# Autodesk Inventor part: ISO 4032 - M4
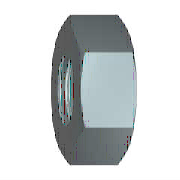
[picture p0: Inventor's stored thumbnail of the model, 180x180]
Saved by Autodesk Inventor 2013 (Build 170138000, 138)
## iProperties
Created: 2012-02
Part Number: ISO 4032 - M4
Material: Edelstahl, 440C
Description: Sechskantmuttern, Typ 1 - Produktklasse A und B
Document SubType Name: Modeling
Standard: ISO 4032
Designer: rYan
Standard Revision: Third edition 1999-08-15
Standards Organization: ISO
Language: de-DE
Size Designation: M4
Categories: <MemberInstance><Categories><Category DisplayName="Verbindungselemente" InternalName="e4da775c-781d-43d5-af7c-5136215cf5a6" Mnemonic="FSTN"><Category DisplayNam
Density: 7.75 g/cm^3
IsCustomPart: 0
Author: rYan
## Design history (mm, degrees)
sketch "Skizze1"
  geometry: L1 (-4.041, 0)-(-2.021, 3.5); L2 (-2.021, 3.5)-(2.021, 3.5); L3 (2.021, 3.5)-(4.041, 0); L4 (4.041, 0)-(2.021, -3.5); L5 (2.021, -3.5)-(-2.021, -3.5); L6 (-2.021, -3.5)-(-4.041, 0); 2 further points
  constraints: 12 end point, 1 coincident, 1 horizontal, 11 other
  dimensions: "d0" = 8.0829 distance of L3.end L1.start (= 1.1547 x SW)
extrude "Körper" new body sketch "Skizze1" distance "d1" = 3.2 (= KOH); taper "d2" = 0 deg
sketch "Skizze2"
  geometry: L1 (0, 2.021)-(0, 4.041) reference; L2 (0, 4.041)-(3.2, 4.041) reference; L3 (3.2, 2.021)-(3.2, 4.041) reference; L4 (-0.64, 0)-(3.84, 0) reference; L5 (0.63, 4.041)-(0, 2.95); L6 (2.57, 4.041)-(3.2, 2.95)
  constraints: 4 end point, 4 point on line
  dimensions: "d3" = 30 deg angle of L1 L5 (= ANG1); "d4" = 30 deg angle of L3 L6 (= ANG2); "d5" = 5.9 diameter of L5.end L4 (= SW0); "d6" = 5.9 diameter of L6.end L4 (= SW01)
revolve "Fase1" sketch "Skizze2" stored, may be unused: angle "d7" = 90 deg
sketch "Skizze3"
  geometry: 4 further points
  constraints: 1 coincident, 1 other
hole "Gewinde" sketch "Skizze3" at (0, 0) diameter "d25" = 3.242; stored, may be unused: countersink angle "d29" = 82 deg, drill point angle "d31" = 118 deg; dims "d26" = 6, "d27" = 4, "d28" = 2, "d30" = 8
workaxis "Work Axis1"
workplane "Work Plane1"
body "Solid1"
chamfer "Fase2" distance "d8" = 0.37889 (= -0.5 x GD1 + 0.5 x NND); stored, may be unused: angle "d9" = 30 deg, second distance "d40" = 0.37889 (= -0.5 x GD1 + 0.5 x NND)
chamfer "Fase3" distance "d10" = 0.37889 (= -0.5 x GD1 + 0.5 x NND); stored, may be unused: angle "d11" = 30 deg, second distance "d41" = 0.37889 (= -0.5 x GD1 + 0.5 x NND)
other parameters: "ANG1" = 30 deg [user parameter; used in 1 equation term], "ANG2" = 30 deg [user parameter; used in 1 equation term], "NND" = 4 [user parameter; used in 4 equation terms], "KOH" = 3.2 [user parameter; used in 1 equation term], "SW" = 7 [user parameter; used in 2 equation terms], "SW0" = 5.9 [user parameter; used in 2 equation terms], "SW01" = 5.9 (= SW0) [user parameter; used in 1 equation term], "GD1" = 3.24223 (computed from THREADDIA, PTC, TOA) [user parameter; used in 4 equation terms], "d13" = 0, "d14" = 0, "d39" = 0, "d42" = 0, "GUL" = 0.37889 (= 0.541266 x PTC) [user parameter], "TPU" = 14.28571 (computed from PTC) [user parameter], "THREADDIA" = 4 [user parameter; used in 1 equation term], "TOA" = 30 deg [user parameter; used in 1 equation term], "PTC" = 0.7 [user parameter; used in 4 equation terms], "E0" = 8.085 (= 1.155 x SW) [user parameter], "GAL" = 0.37889 (= 0.541266 x PTC) [user parameter]
